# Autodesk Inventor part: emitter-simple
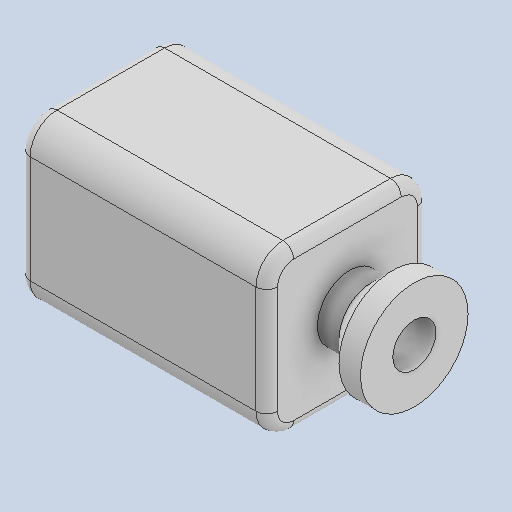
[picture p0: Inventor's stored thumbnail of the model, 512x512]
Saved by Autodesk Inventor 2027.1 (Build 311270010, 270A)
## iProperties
Created: 2026-07
Part Number: emitter-simple
Material: Generic
Document SubType Name: Modeling
Designer: dunge
Density: 1 g/cm^3
Appearance: Default
Author: dunge
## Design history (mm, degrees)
sketch "Sketch1"
  geometry: L1 (16.089, 9.798)-(-15.661, 9.798); L2 (-15.661, 9.798)-(-15.661, -9.252); L3 (-15.661, -9.252)-(16.089, -9.252); L4 (16.089, -9.252)-(16.089, 9.798); 1 further point
  constraints: 8 end point, 2 parallel, 1 horizontal, 1 perpendicular
  dimensions: "d0" = 19.05 distance of L3.end L1.start; "d1" = 31.75 distance of L1.start L1.end
extrude "Extrusion1" new body sketch "Sketch1" distance "d2" = 19.05; taper "d3" = 0 deg
sketch "Sketch2"
  geometry: C1 r 3.81 at (9.798, 9.516); 1 further point
  constraints: 1 centre point
  dimensions: "d4" = 7.62 diameter of C1
extrude "Extrusion2" join sketch "Sketch2" distance "d5" = 5.08; taper "d6" = 0 deg
sketch "Sketch3"
  geometry: C1 r 2.54 at (0, 0); 1 further point
  constraints: 1 centre point
  dimensions: "d10" = 5.08 diameter of C1
extrude "Extrusion3" cut sketch "Sketch3" distance "d11" = 16.1925; taper "d12" = 0 deg
fillet "Fillet1" dims "d13" = 3.175
sketch "Sketch4"
  geometry: C1 r 3.81 at (0, 0); C2 r 6.35 at (0, 0); 1 further point
  constraints: 2 centre point, 1 coincident
  dimensions: "d14" = 2.54 radial gap between concentric circles of C2 C1; "d15" = 7.62 diameter of C1
extrude "Extrusion4" join sketch "Sketch4" distance "d16" = 2.54; taper "d17" = 0 deg
chamfer "Chamfer2" distance "d18" = 2.54; stored, may be unused: second distance "d19" = 3.175, angle "d20" = 45 deg
sketch "Sketch6"
  geometry: L1 (0, 19.05)-(12.7, 19.05) reference; L2 (15.875, 3.175)-(15.875, 15.875) reference; L3 (0, 19.05)-(12.7, 19.05) reference; L4 (-3.175, 3.175)-(-3.175, 15.875) reference; L5 (0, 0)-(12.7, 0) reference; C1 r 3.81 at (6.623, 9.516) reference; C2 r 3.81 at (6.623, 9.516) reference; A1 r 3.175 centre (12.7, 3.175) between (12.7, 0) and (15.875, 3.175) reference; A2 r 3.175 centre (12.7, 15.875) between (15.875, 15.875) and (12.7, 19.05) reference; A3 r 3.175 centre (0, 15.875) between (0, 19.05) and (-3.175, 15.875) reference; A4 r 3.175 centre (0, 3.175) between (-3.175, 3.175) and (0, 0) reference; 3 further points
extrude "Extrusion5" cut sketch "Sketch6" distance "d21" = 2.54; taper "d22" = 0 deg
fillet "Fillet2" dims "d23" = 1.27
body "Solid1"
node "Projected Loop1"
